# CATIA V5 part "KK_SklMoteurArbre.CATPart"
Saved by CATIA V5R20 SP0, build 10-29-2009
Part number: skl moteur plus arbre
Bounding box of the stored display mesh (mm): x 0 to 0, y 0 to 0, z -60 to 0
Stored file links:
  G:\Khaled_CFAO_2011\ST2M\ST2M_GR2\tcorbin\Khaled\CAD_ThinkMOTION\KK_SklMoteurArbre.CATPart
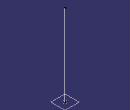
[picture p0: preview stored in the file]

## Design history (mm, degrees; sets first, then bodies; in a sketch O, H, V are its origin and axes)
Line1 "droite_axe_moteur": type PtPt, FirstPoint Point1, SecondPoint Point2
Body1 (main body)
  Plane1 "plan_extr_disque": stored without definition
  Plane2 "plan_extr_arbre": type Offset, RefPlane Plane1, Offset -60
  Point1 "point_centre_arbre": type OnPlane, Support Plane2, H 0, V 0, Direction (1, 0, 0)
  Point2 "point_origine_disque": stored without definition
